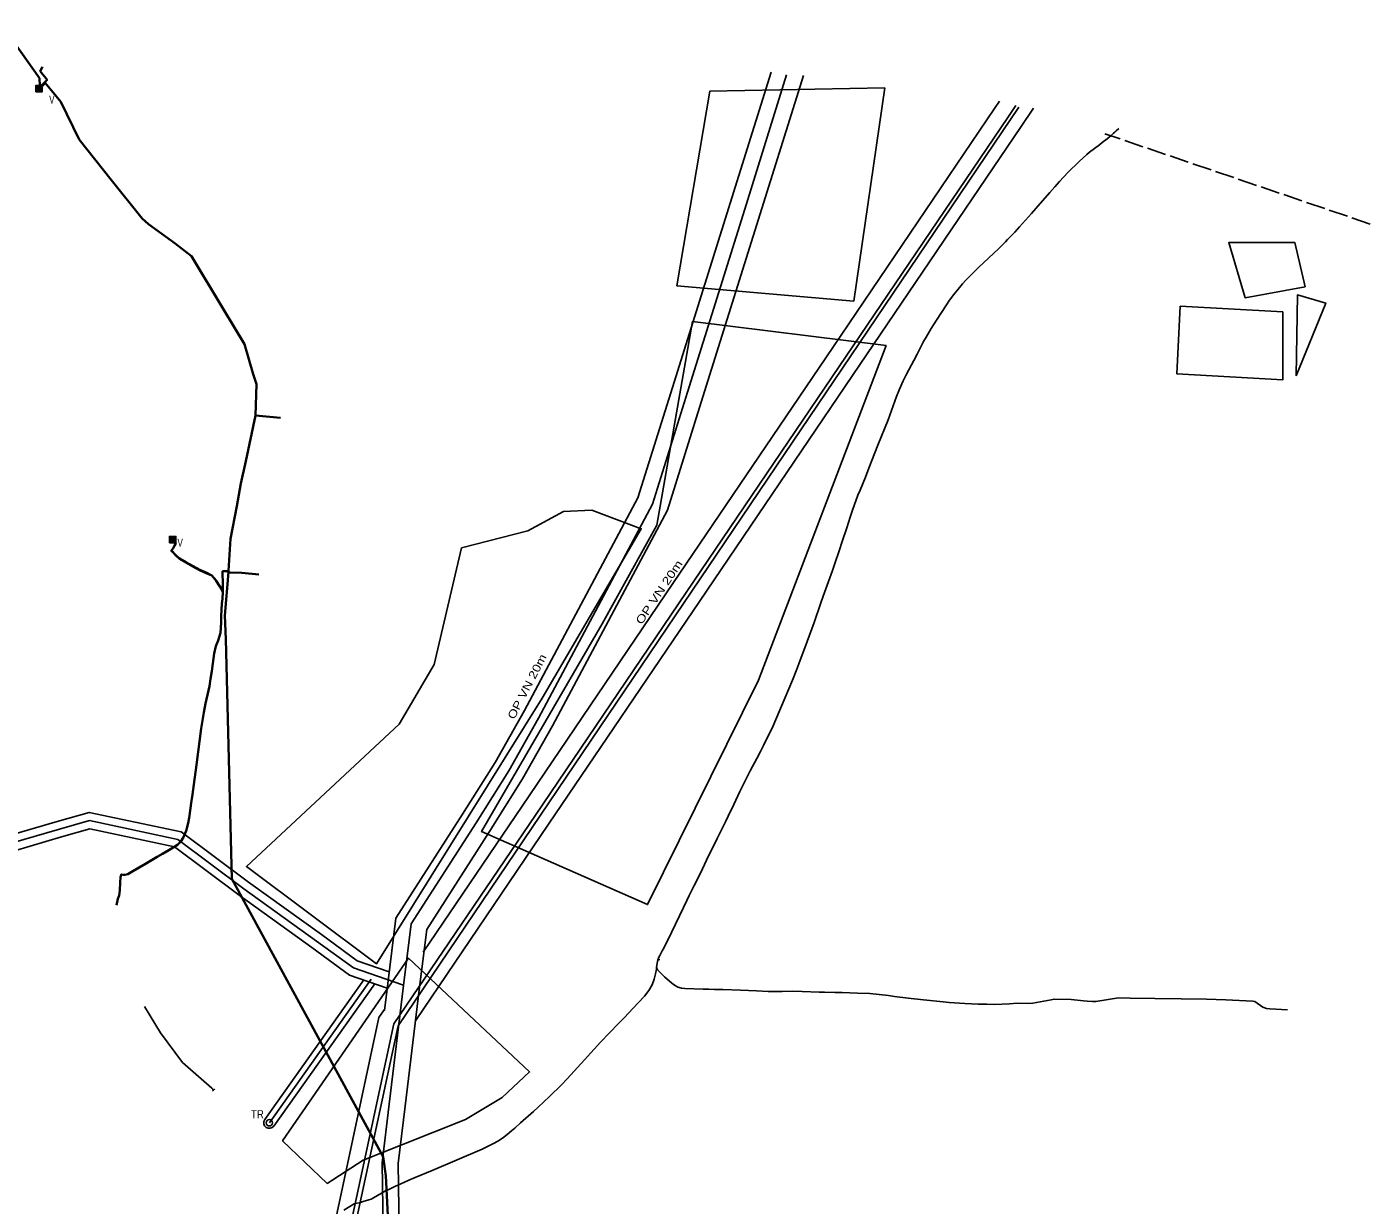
# Model space of a CAD drawing. Extents: x -589836 to -586543, y -1119607 to -1116793.
# Drawn here: x -588693 to -587015, y -1118266 to -1116793 of the extents above; entities that cross this region are included whole.
import ezdxf

# ---------------------------------------------------------------- set-up
doc = ezdxf.new("R2010")
doc.units = 0
doc.header["$LTSCALE"] = 4
doc.linetypes.add('LONG_DASHED', pattern=[7.5, 6, -1.5])
for name, color, linetype, lineweight in [('21', 7, 'Continuous', 25), ('22', 7, 'Continuous', 25), ('23', 7, 'Continuous', 25), ('24', 7, 'Continuous', 25), ('25', 7, 'Continuous', 25), ('26', 7, 'Continuous', 25), ('28', 7, 'Continuous', 25), ('29', 7, 'Continuous', 25), ('31', 7, 'Continuous', 25), ('45', 7, 'Continuous', 25), ('49', 7, 'Continuous', 25)]:
    doc.layers.add(name, color=color, linetype=linetype, lineweight=lineweight)

msp = doc.modelspace()

# ---------------------------------------------------------------- hatches: boundary and pattern name
at = {"layer": '49'}
for points in [[(-588682.471, -1116874.254), (-588674.471, -1116874.254), (-588674.471, -1116866.254), (-588682.471, -1116866.254)], [(-588515.276, -1117437.866), (-588507.276, -1117437.866), (-588507.276, -1117429.866), (-588515.276, -1117429.866)]]:
    msp.add_hatch(color=256, dxfattribs=at).paths.add_polyline_path(points)

# ---------------------------------------------------------------- linework, layer by layer
at = {"layer": '21'}
msp.add_line((-587744.171, -1116853.013), (-587796.146, -1117020.89), dxfattribs=at)
for points in [[(-587457.391, -1116891.203), (-587467.495, -1116906.128), (-587678.431, -1117217.658), (-587869.495, -1117499.964), (-588057.978, -1117778.27), (-588234.704, -1118039.283), (-588299.251, -1118339.426), (-588366.538, -1118652.377), (-588434.124, -1118966.627), (-588505.333, -1119297.805), (-588563.874, -1119569.266)], [(-588222.732, -1117991.024), (-588213.078, -1117914.074), (-588132.06, -1117787.968), (-588091.18, -1117722.838), (-588054.16, -1117656.966), (-587911.485, -1117389.446), (-587867.746, -1117249.494), (-587796.146, -1117020.89)], [(-588905.15, -1118052.338), (-588901.267, -1117923.545), (-588757.466, -1117838.815), (-588713.012, -1117813.46), (-588652.783, -1117795.811), (-588615.102, -1117785.14), (-588504.766, -1117808.551), (-588422.318, -1117870.318), (-588331.332, -1117935.642), (-588285.464, -1117969.199), (-588224.037, -1117990.567), (-588222.732, -1117991.024)], [(-588222.732, -1117991.024), (-588240.555, -1118139.541), (-588249.547, -1118212.86), (-588245.083, -1118520.625), (-588241.831, -1118769.889), (-588238.396, -1119016.784), (-588268.401, -1119319.835), (-588280.072, -1119439.07)]]:
    msp.add_lwpolyline(points, dxfattribs=at)
at = {"layer": '22'}
msp.add_line((-588242.59, -1117988.641), (-588246.671, -1118022.649), dxfattribs=at)
for points in [[(-587763.433, -1116849.529), (-587886.834, -1117243.522), (-587930.015, -1117381.69), (-588071.703, -1117647.36), (-588108.378, -1117712.616), (-588148.944, -1117777.246), (-588232.358, -1117907.082), (-588242.576, -1117988.534)], [(-588202.888, -1117993.514), (-588193.798, -1117921.066), (-588115.176, -1117798.69), (-588073.982, -1117733.06), (-588036.617, -1117666.572), (-587892.955, -1117397.202), (-587848.658, -1117255.466), (-587722.855, -1116853.801)], [(-587478.009, -1116885.983), (-587484.056, -1116894.915), (-587694.993, -1117206.446), (-587886.056, -1117488.752), (-588074.538, -1117767.056), (-588198.119, -1117949.577)], [(-588207.822, -1118035.252), (-588041.418, -1117789.484), (-587852.934, -1117511.176), (-587661.869, -1117228.87), (-587450.934, -1116917.341), (-587435.416, -1116894.419)], [(-588240.773, -1117974.158), (-588280.766, -1117960.245), (-588325.464, -1117927.545), (-588416.403, -1117862.254), (-588500.534, -1117799.226), (-588615.446, -1117774.844), (-588655.551, -1117786.202), (-588716.949, -1117804.193), (-588762.482, -1117830.164), (-588911.096, -1117917.73), (-588915.145, -1118052.037)], [(-588895.155, -1118052.639), (-588891.438, -1117929.36), (-588752.45, -1117847.466), (-588709.075, -1117822.727), (-588650.015, -1117805.42), (-588614.758, -1117795.436), (-588508.998, -1117817.876), (-588428.233, -1117878.382), (-588337.2, -1117943.739), (-588290.162, -1117978.153), (-588243.318, -1117994.447)], [(-588260.167, -1119441.018), (-588248.497, -1119321.794), (-588218.382, -1119017.633), (-588221.833, -1118769.619), (-588225.085, -1118520.35), (-588229.529, -1118213.937), (-588220.701, -1118141.95), (-588202.874, -1117993.407)], [(-588246.811, -1118021.492), (-588253.441, -1118031.284), (-588318.804, -1118335.221), (-588386.091, -1118648.172), (-588453.677, -1118962.422), (-588524.885, -1119293.595), (-588565.713, -1119482.918)]]:
    msp.add_lwpolyline(points, dxfattribs=at)
at = {"layer": '23'}
msp.add_line((-588263.145, -1117983.106), (-588390.44, -1118162.844), dxfattribs=at)
at = {"layer": '24'}
for p, q in [((-588272.553, -1117984.278), (-588396.152, -1118158.798)), ((-588384.728, -1118166.89), (-588258.789, -1117989.066))]:
    msp.add_line(p, q, dxfattribs=at)
msp.add_arc((-588390.44, -1118162.844), 7, 144.68879, 324.68879, dxfattribs=at)
at = {"layer": '25'}
msp.add_lwpolyline([(-587453.687, -1116893.154), (-588229.609, -1118041.457), (-588558.571, -1119570.952)], dxfattribs=at)
at = {"layer": '26'}
for p, q in [((-587728.88, -1117589.33), (-587731.35, -1117595.91)), ((-587904.6, -1117958.39), (-587903.26, -1117958.51)), ((-587903.26, -1117958.51), (-587903.35, -1117959.53))]:
    msp.add_line(p, q, dxfattribs=at)
for points in [[(-587329.001, -1116920.076), (-587332.08, -1116922.73), (-587334.03, -1116924.36), (-587335.52, -1116925.84), (-587338.43, -1116928.68)], [(-587338.43, -1116928.68), (-587343.31, -1116932.98), (-587349.55, -1116937.67)], [(-587349.55, -1116937.67), (-587352.88, -1116940.2), (-587365.51, -1116949.58), (-587368.98, -1116952.51), (-587378.4, -1116961.08), (-587392.37, -1116975.16), (-587402.98, -1116986.33), (-587408.94, -1116992.93), (-587415.27, -1117000.15), (-587426.94, -1117013.8), (-587437.9, -1117026.28), (-587453.06, -1117043.04), (-587458.8, -1117049.51), (-587467.78, -1117058.79), (-587470.6, -1117061.8), (-587479.3, -1117070.38), (-587503.87, -1117093.17), (-587519.92, -1117109.48), (-587524.14, -1117114.14), (-587535.16, -1117127.53), (-587540.51, -1117134.64), (-587544.41, -1117140.32), (-587556.84, -1117159.37), (-587563.4, -1117169.9), (-587569.7, -1117180.7), (-587572.99, -1117186.38), (-587577.86, -1117196.24), (-587580.8, -1117202.12)], [(-587580.8, -1117202.12), (-587584.82, -1117209.87), (-587594.04, -1117226.91), (-587598.43, -1117235.51), (-587603.04, -1117245.78), (-587606.59, -1117255.12), (-587617.17, -1117284.18), (-587629.82, -1117315.79), (-587641.24, -1117344.59), (-587645.6, -1117355.64), (-587652.22, -1117371.91), (-587654.83, -1117378.36), (-587661.6, -1117397.03), (-587664.54, -1117405.62), (-587668.86, -1117419.31), (-587674.54, -1117436.32), (-587678.27, -1117447.83), (-587683.7, -1117463.52), (-587686.85, -1117472.31)], [(-587686.85, -1117472.31), (-587698.26, -1117504.49), (-587701.6, -1117514.26), (-587709.72, -1117537.67), (-587718.4, -1117561.4), (-587728.88, -1117589.33)], [(-587731.35, -1117595.91), (-587736.48, -1117609.4), (-587745.62, -1117631.42), (-587757.37, -1117658.59), (-587760.9, -1117666.48), (-587773.11, -1117691.38)], [(-587773.11, -1117691.38), (-587776.57, -1117698.68), (-587781.14, -1117707.27), (-587789.47, -1117723.01), (-587796.5, -1117737.06), (-587802.35, -1117748.84), (-587810.01, -1117765.11), (-587817, -1117779.44), (-587820.58, -1117786.77), (-587823.45, -1117792.65), (-587830.94, -1117807.56), (-587844.21, -1117834.53), (-587851.83, -1117850.63), (-587859.44, -1117866.42), (-587865.77, -1117878.89), (-587868.76, -1117884.94), (-587872.86, -1117893.56), (-587888.06, -1117924.96), (-587897.47, -1117944.54), (-587899.38, -1117947.9), (-587902.57, -1117953.53), (-587903.7, -1117955.91), (-587904.6, -1117958.39)], [(-587906.63, -1117968.2), (-587905.35, -1117961.41), (-587904.6, -1117958.39)], [(-588297.36, -1118272.24), (-588284.44, -1118264.16), (-588276.55, -1118262.4), (-588273.05, -1118261.28), (-588266.04, -1118259.3), (-588263.02, -1118258.17), (-588260.32, -1118256.7), (-588245.44, -1118248.05), (-588242.04, -1118246.45), (-588232.96, -1118241.86), (-588222.33, -1118237.45), (-588216.01, -1118234.38), (-588208.19, -1118231.04), (-588187.08, -1118222.65), (-588124.34, -1118195.88), (-588110.21, -1118188.84), (-588104.76, -1118185.93), (-588098.97, -1118181.91), (-588093.38, -1118177.49), (-588087.72, -1118173.03), (-588083.67, -1118169.53), (-588076.38, -1118163), (-588060.28, -1118148.67), (-588054.39, -1118143.21), (-588040.37, -1118129.87), (-588025.37, -1118115.38), (-588018.2, -1118108.07), (-587996.4, -1118084.14), (-587976.67, -1118062.24), (-587954.2, -1118038.72), (-587946.8, -1118031.34), (-587936.01, -1118020.11), (-587921.62, -1118004.37), (-587916.06, -1117997.65), (-587912.03, -1117990.29), (-587909.55, -1117983.29), (-587907.79, -1117976.48), (-587906.45, -1117970.8), (-587906.63, -1117968.2)], [(-587906.63, -1117968.2), (-587905.42, -1117971.46), (-587896.61, -1117980.25), (-587890.39, -1117985.85), (-587885.3, -1117989.79), (-587880.127, -1117993.13), (-587875.26, -1117994.63), (-587871.36, -1117995.07), (-587848.13, -1117995.88), (-587841.32, -1117995.96), (-587834.33, -1117996.36), (-587823.59, -1117996.33), (-587801.57, -1117997.06), (-587781.46, -1117998), (-587767.01, -1117998.547), (-587749.69, -1117998.66), (-587737.07, -1117998.51), (-587724.72, -1117998.827), (-587703.33, -1117999.58), (-587696.76, -1117999.46), (-587683.7, -1118000.09), (-587674.73, -1117999.9), (-587655.353, -1118000.99), (-587639.97, -1118001.41), (-587616.88, -1118003.59), (-587609.21, -1118004.94), (-587592.27, -1118007.06), (-587573.06, -1118009), (-587548.47, -1118011.52), (-587541.01, -1118012.34), (-587521.45, -1118013.73), (-587504.58, -1118014.64), (-587500, -1118014.581), (-587493.62, -1118014.5), (-587484.42, -1118014.89), (-587465.44, -1118014.11), (-587455.96, -1118013.45), (-587442.64, -1118013.73), (-587436.13, -1118013.13)], [(-587436.13, -1118013.13), (-587413.43, -1118009.08), (-587409.73, -1118008.17), (-587388.38, -1118008.52), (-587372.84, -1118010.31), (-587368.41, -1118010.64), (-587361.887, -1118011.15), (-587357.61, -1118011.04), (-587329.32, -1118006.82), (-587314.56, -1118006.89)], [(-587314.56, -1118006.89), (-587283.813, -1118007.27), (-587250.77, -1118008.08), (-587219.15, -1118008.47), (-587195.16, -1118009.29), (-587161.53, -1118010.7), (-587158.69, -1118011.22), (-587148.68, -1118018.14), (-587144.1, -1118020.18), (-587140.1, -1118020.567), (-587118.01, -1118021.45)]]:
    msp.add_lwpolyline(points, dxfattribs=at)
at = {"layer": '28'}
msp.add_circle((-588390.44, -1118162.844), 4, dxfattribs=at)
at = {"layer": '31'}
for p, q in [((-588546.31, -1118017.42), (-588526.55, -1118050.52)), ((-588526.55, -1118050.52), (-588499.13, -1118087.56)), ((-588499.13, -1118087.56), (-588462.26, -1118119.55)), ((-588462.26, -1118119.55), (-588460.38, -1118121.65)), ((-588461.311, -1118122.483), (-588460.566, -1118123.316))]:
    msp.add_line(p, q, dxfattribs=at)
msp.add_lwpolyline([(-588461.311, -1118122.483), (-588460.38, -1118121.65), (-588459.45, -1118120.817), (-588458.704, -1118121.649)], dxfattribs=at)
at = {"layer": '45', "linetype": 'LONG_DASHED'}
msp.add_line((-587014.774, -1117039.365), (-587346.199, -1116926.583), dxfattribs=at)
at = {"layer": '45'}
for points in [[(-587621.349, -1116868.973), (-587660.062, -1117135.768), (-587881.153, -1117116.834), (-587839.859, -1116873.276)], [(-587095.933, -1117117.693), (-587170.777, -1117131.463), (-587191.424, -1117062.613), (-587108.837, -1117062.613)], [(-587107.189, -1117229.269), (-587105.614, -1117128.024), (-587070.269, -1117138.129)], [(-587123.896, -1117149.11), (-587123.896, -1117234.312), (-587256.379, -1117226.566), (-587252.077, -1117142.225)], [(-587779.349, -1117609.544), (-587917.855, -1117890.112), (-588125.184, -1117798.884), (-587974.634, -1117538.971), (-587906.242, -1117415.899), (-587861.504, -1117161.15), (-587619.764, -1117191.273)], [(-588049.479, -1117631.92), (-588256.377, -1117964.126), (-588419.187, -1117842.347), (-588228.418, -1117664.624), (-588184.544, -1117590.178), (-588150.133, -1117444.301), (-588067.545, -1117422.785), (-588022.81, -1117398.687), (-587987.538, -1117396.966), (-587925.598, -1117420.203)], [(-588273.367, -1118209.409), (-588318.102, -1118238.671), (-588374.021, -1118185.311), (-588216.588, -1117957.241), (-588065.177, -1118099.247), (-588099.589, -1118131.091), (-588145.184, -1118158.631), (-588222.61, -1118189.614)]]:
    msp.add_lwpolyline(points, close=True, dxfattribs=at)
at = {"layer": '49', "lineweight": 35}
for points in [[(-588747.093, -1116792.913), (-588738.762, -1116793.194), (-588715.008, -1116804.206), (-588677.813, -1116857.163), (-588677.489, -1116866.497), (-588677.381, -1116869.624), (-588676.754, -1116868.066), (-588668.33, -1116859.28), (-588676.84, -1116848.14), (-588673.916, -1116842.778)], [(-588677.381, -1116869.624), (-588676.372, -1116869.229), (-588672.39, -1116865.04), (-588670.47, -1116863.02), (-588651.03, -1116886.77), (-588627.97, -1116933.78), (-588588.3, -1116984.26), (-588549.58, -1117032.35), (-588541.49, -1117039.49), (-588508.05, -1117063.81), (-588487.95, -1117079.49), (-588448.15, -1117145.56), (-588421.49, -1117189.62), (-588410.82, -1117227.09), (-588406.65, -1117239.57), (-588407.85, -1117278.79), (-588376.576, -1117281.6)], [(-588407.85, -1117278.79), (-588420.01, -1117335.69), (-588426.19, -1117363.76), (-588431.22, -1117391.91), (-588438.98, -1117432.71), (-588441.594, -1117472.758), (-588441.71, -1117474.54), (-588439.65, -1117474.77), (-588424.637, -1117475.569), (-588403.568, -1117477.406)], [(-588441.71, -1117474.54), (-588442.195, -1117474.501), (-588442.72, -1117473.78), (-588443.95, -1117473.3), (-588448.82, -1117473.35), (-588448.48, -1117490.8), (-588448.573, -1117496.211), (-588448.61, -1117498.35), (-588451.87, -1117492.36), (-588456.72, -1117485.03), (-588462.14, -1117478.54), (-588468.49, -1117475.55), (-588477.46, -1117471.73), (-588494.7, -1117461.88), (-588502.67, -1117457.45), (-588507.38, -1117453.27), (-588512.67, -1117447.65), (-588510.67, -1117444.76), (-588509.07, -1117441.55), (-588507.39, -1117438.68), (-588509.85, -1117436.65), (-588510.411, -1117436.237), (-588511.486, -1117434.608), (-588510.766, -1117436.211), (-588510.125, -1117436.747), (-588507.67, -1117438.69), (-588510.86, -1117444.63), (-588513.06, -1117447.77), (-588510.42, -1117450.36), (-588507.69, -1117453.51), (-588502.9, -1117457.81), (-588486.24, -1117467.4), (-588477.63, -1117472.16), (-588468.66, -1117476.03), (-588462.41, -1117478.91), (-588457.11, -1117485.29), (-588452.32, -1117492.62), (-588448.74, -1117499.16), (-588449.05, -1117507.85), (-588449.82, -1117513.74), (-588450.17, -1117521.83), (-588450.77, -1117529.44), (-588450.61, -1117537.27), (-588451.7, -1117550.5), (-588454.39, -1117560.05), (-588457.52, -1117567.13), (-588459.4, -1117576.4), (-588461.12, -1117588.84), (-588462.47, -1117598.12), (-588464.18, -1117608.07), (-588465.39, -1117617.11), (-588470.15, -1117638.52), (-588472.39, -1117649.81), (-588475.52, -1117669.9), (-588481.52, -1117715.35), (-588484.68, -1117740.15), (-588486.51, -1117752.47), (-588487.74, -1117760.42), (-588490.64, -1117781.79), (-588492.06, -1117788.13), (-588494.23, -1117797.8), (-588497.99, -1117806.62), (-588500.99, -1117811.23), (-588505.44, -1117815.47), (-588515.87, -1117822.07), (-588523.95, -1117826.75), (-588530.84, -1117830.6), (-588545.09, -1117839.16), (-588561.02, -1117848.28), (-588567.35, -1117851.9), (-588571.02, -1117852.73), (-588571.21, -1117852.77), (-588573.01, -1117852.72), (-588575.54, -1117852.4), (-588575.57, -1117853.39), (-588576.329, -1117855.701), (-588577.04, -1117862.5), (-588577.36, -1117872.66), (-588578.22, -1117878.89), (-588579.84, -1117883.06), (-588581.427, -1117890.885)], [(-588441.71, -1117474.54), (-588446.09, -1117528.74), (-588444.76, -1117558.39), (-588437.14, -1117857.91), (-588248.114, -1118205.264), (-588244.69, -1118228.95), (-588227.86, -1118568.33), (-588227.89, -1118904.6), (-588221.46, -1119036.99), (-588291.911, -1119465.134)]]:
    msp.add_lwpolyline(points, dxfattribs=at)
at = {"layer": '49'}
for points in [[(-588682.471, -1116874.254), (-588674.471, -1116874.254), (-588674.471, -1116866.254), (-588682.471, -1116866.254)], [(-588515.276, -1117437.866), (-588507.276, -1117437.866), (-588507.276, -1117429.866), (-588515.276, -1117429.866)]]:
    msp.add_lwpolyline(points, close=True, dxfattribs=at)

# ---------------------------------------------------------------- texts
at = {"layer": '22'}
for rotation, width, p in [(56.127, 1.3, (-587925.13, -1117540.906)), (62.65, 1.25, (-588084.502, -1117659.484))]:
    msp.add_text('OP VN 20m', height=10, rotation=rotation, dxfattribs=dict(at, width=width)).set_placement(p)
at = {"layer": '29', "width": 0.9}
msp.add_text('TR', height=10, dxfattribs=at).set_placement((-588413.426, -1118157.11))
at = {"layer": '49', "width": 0.75}
for p in [(-588665.611, -1116888.749), (-588505.262, -1117442.813)]:
    msp.add_text('V', height=10, dxfattribs=at).set_placement(p)

doc.saveas('drawing.dxf')
